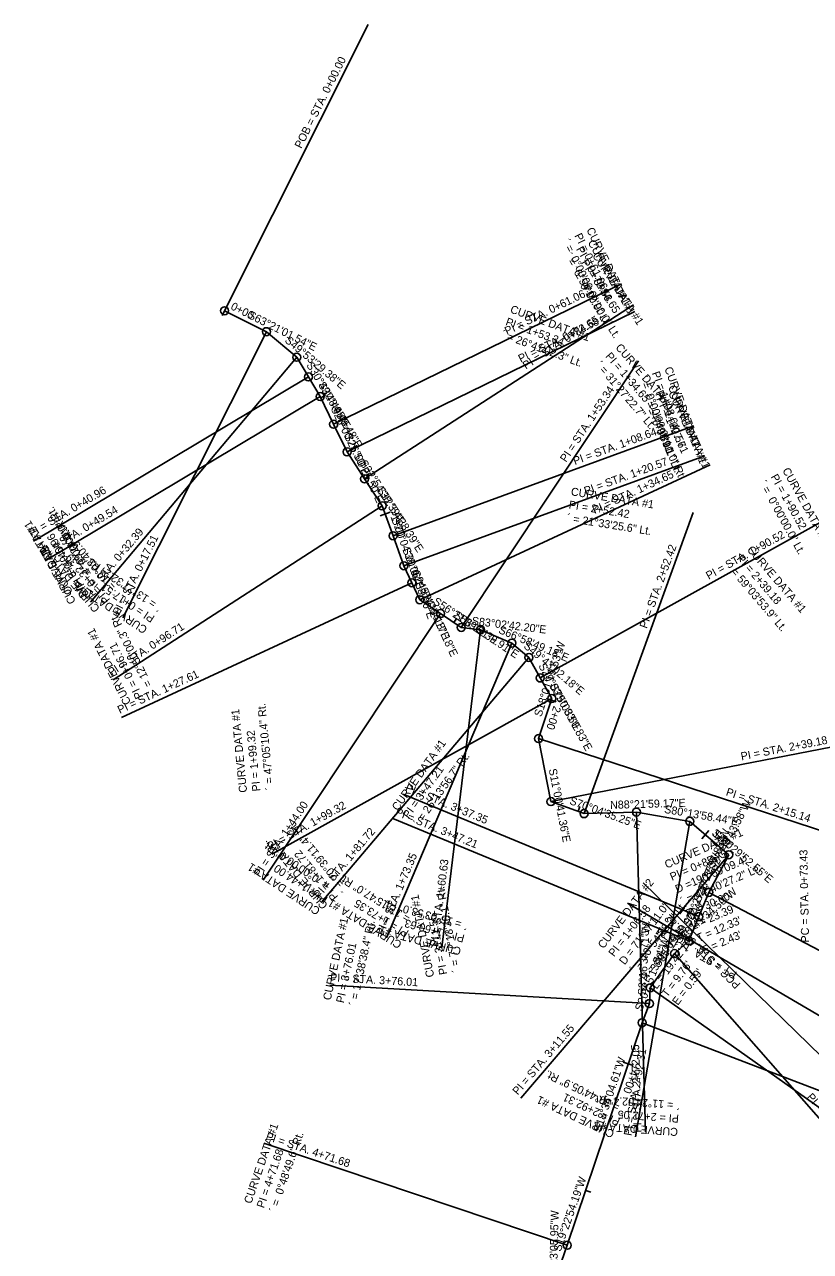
# Model space of a CAD drawing. Extents: x 1158784 to 1165006, y 610007 to 611539.
# Drawn here: x 1162723.7 to 1163018.2, y 610487.8 to 610947.6 of the extents above; entities that cross this region are included whole.
import ezdxf

# ---------------------------------------------------------------- set-up
doc = ezdxf.new("R2010")
doc.units = 0
for name, color, linetype in [('D_Roadway_Centerline', 7, 'Continuous'), ('D_Roadway_Centerline_Bearings', 7, 'Continuous'), ('D_Roadway_Centerline_CurveData', 7, 'Continuous'), ('D_Roadway_Centerline_Flags', 7, 'Continuous'), ('D_Roadway_Centerline_Text', 7, 'Continuous')]:
    doc.layers.add(name, color=color, linetype=linetype)

msp = doc.modelspace()

# ---------------------------------------------------------------- linework, layer by layer
at = {"layer": 'D_Roadway_Centerline'}
for p, q in [((1162798.64, 610840.35), (1162814.29, 610832.5)), ((1162814.29, 610832.5), (1162825.67, 610822.91)), ((1162825.67, 610822.91), (1162830.06, 610815.55)), ((1162830.06, 610815.55), (1162834.46, 610808.18)), ((1162834.46, 610808.18), (1162839.51, 610797.83)), ((1162839.51, 610797.83), (1162844.56, 610787.47)), ((1162844.56, 610787.47), (1162851.11, 610777.35)), ((1162851.11, 610777.35), (1162857.67, 610767.22)), ((1162857.67, 610767.22), (1162861.76, 610756.01)), ((1162861.76, 610756.01), (1162865.86, 610744.8)), ((1162865.86, 610744.8), (1162868.83, 610738.42)), ((1162868.83, 610738.42), (1162871.79, 610732.03)), ((1162871.79, 610732.03), (1162879.57, 610726.86)), ((1162879.57, 610726.86), (1162887.35, 610721.68)), ((1162887.35, 610721.68), (1162894.58, 610720.8)), ((1162894.58, 610720.8), (1162906.29, 610715.82)), ((1162906.29, 610715.82), (1162912.68, 610710.41)), ((1162912.68, 610710.41), (1162916.95, 610702.72)), ((1162916.95, 610702.72), (1162921.23, 610695.03)), ((1162921.23, 610695.03), (1162916.33, 610679.99)), ((1162916.33, 610679.99), (1162920.92, 610656.39)), ((1162920.92, 610656.39), (1162933.37, 610651.88)), ((1162933.37, 610651.88), (1162953, 610652.44)), ((1162953, 610652.44), (1162972.95, 610649)), ((1162972.95, 610649), (1162987.59, 610636.5)), ((1162987.59, 610636.5), (1162980.17, 610622.39)), ((1162980.17, 610622.39), (1162976.4, 610613.28)), ((1162976.4, 610613.28), (1162972.64, 610604.17)), ((1162972.64, 610604.17), (1162967.25, 610599.44)), ((1162967.25, 610599.44), (1162958.16, 610586.62)), ((1162958.16, 610586.62), (1162957.82, 610580.71)), ((1162957.82, 610580.71), (1162955.09, 610573.54)), ((1162955.09, 610573.54), (1162927.06, 610490.12)), ((1162927.06, 610490.12), (1162924.92, 610484.02))]:
    msp.add_line(p, q, dxfattribs=at)
at = {"layer": 'D_Roadway_Centerline_Flags'}
for points in [[(1162798.64, 610840.35), (1162852.46, 610947.6)], [(1162839.51, 610797.83), (1162947.36, 610850.44)], [(1162844.56, 610787.47), (1162952.41, 610840.09)], [(1162851.11, 610777.35), (1162951.86, 610842.54)], [(1162814.29, 610832.5), (1162760.46, 610725.24)], [(1162825.67, 610822.91), (1162748.36, 610731.13)], [(1162887.35, 610721.68), (1162953.82, 610821.59)], [(1162830.06, 610815.55), (1162727.02, 610754.05)], [(1162834.46, 610808.18), (1162731.41, 610746.68)], [(1162861.76, 610756.01), (1162974.47, 610797.21)], [(1162865.86, 610744.8), (1162978.57, 610786)], [(1162871.79, 610732.03), (1162980.63, 610782.57)], [(1162857.67, 610767.22), (1162756.93, 610702.02)], [(1162933.37, 610651.88), (1162974.26, 610764.7)], [(1162916.95, 610702.72), (1163021.84, 610761.02)], [(1162868.83, 610738.42), (1162759.98, 610687.89)], [(1162879.57, 610726.86), (1162813.09, 610626.95)], [(1162894.58, 610720.8), (1162880.05, 610601.68)], [(1162906.29, 610715.82), (1162859.37, 610605.38)], [(1162912.68, 610710.41), (1162835.09, 610618.87)], [(1162921.23, 610695.03), (1162816.34, 610636.74)], [(1162916.33, 610679.99), (1163030.44, 610642.86)], [(1162920.92, 610656.39), (1163038.71, 610679.31)], [(1162976.4, 610613.28), (1162865.5, 610659.13)], [(1162953, 610652.44), (1162956.42, 610532.49)], [(1162972.64, 610604.17), (1162861.74, 610650.02)], [(1162972.95, 610649), (1162952.6, 610530.74)], [(1162987.59, 610636.5), (1162909.65, 610545.26)], [(1163041.46, 610542.25), (1162955.5, 610625.98)], [(1162980.17, 610622.39), (1163086.39, 610566.56)], [(1163053.2, 610557.66), (1162949.63, 610618.28)], [(1162967.25, 610599.44), (1163046.46, 610509.29)], [(1162957.82, 610580.71), (1162838.02, 610587.57)], [(1162958.16, 610586.62), (1163056.06, 610517.22)], [(1162955.09, 610573.54), (1163067.17, 610530.69)], [(1162927.06, 610490.12), (1162813.31, 610528.33)]]:
    msp.add_lwpolyline(points, dxfattribs=at)
for centre in [(1162798.64, 610840.35), (1162814.29, 610832.5), (1162825.67, 610822.91), (1162830.06, 610815.55), (1162834.46, 610808.18), (1162839.51, 610797.83), (1162844.56, 610787.47), (1162851.11, 610777.35), (1162857.67, 610767.22), (1162861.76, 610756.01), (1162865.86, 610744.8), (1162868.83, 610738.42), (1162871.79, 610732.03), (1162879.57, 610726.86), (1162887.35, 610721.68), (1162894.58, 610720.8), (1162906.29, 610715.82), (1162912.68, 610710.41), (1162916.95, 610702.72), (1162921.23, 610695.03), (1162916.33, 610679.99), (1162920.92, 610656.39), (1162933.37, 610651.88), (1162953, 610652.44), (1162972.95, 610649), (1162987.59, 610636.5), (1162980.17, 610622.39), (1162976.4, 610613.28), (1162972.64, 610604.17), (1162967.25, 610599.44), (1162958.16, 610586.62), (1162957.82, 610580.71), (1162955.09, 610573.54), (1162927.06, 610490.12)]:
    msp.add_circle(centre, 1.5, dxfattribs=at)
at = {"layer": 'D_Roadway_Centerline_Text'}
for points in [[(1162799.54, 610842.14), (1162797.74, 610838.56)], [(1162836.46, 610808.65), (1162834.66, 610807.77)], [(1162860.68, 610764.81), (1162856.92, 610763.44)], [(1162885.67, 610725.2), (1162884.57, 610723.53)], [(1162922.92, 610693.77), (1162919.11, 610695)], [(1162931.78, 610654.58), (1162931.09, 610652.7)], [(1162980.1, 610645.53), (1162977.51, 610642.48)], [(1162971.86, 610600.83), (1162970.54, 610602.33)], [(1162951.79, 610557.44), (1162947.99, 610558.71)], [(1162935.86, 610510.04), (1162933.97, 610510.68)]]:
    msp.add_lwpolyline(points, dxfattribs=at)

# ---------------------------------------------------------------- texts
at = {"layer": 'D_Roadway_Centerline_Bearings'}
for s, rotation, p in [('S63%%d21\'01.54"E', 333.3504, (1162807.13, 610837.76)), ('S49%%d53\'29.38"E', 319.8915, (1162820.94, 610828.85)), ('S30%%d49\'48.48"E', 300.8301, (1162829.15, 610820)), ('S30%%d49\'48.48"E', 300.8301, (1162833.55, 610812.63)), ('S26%%d00\'25.50"E', 296.0071, (1162838.33, 610803.66)), ('S26%%d00\'25.50"E', 296.0071, (1162843.38, 610793.31)), ('S32%%d54\'38.39"E', 302.9107, (1162849.1, 610783.22)), ('S32%%d54\'38.39"E', 302.9107, (1162855.65, 610773.1)), ('S20%%d04\'38.06"E', 290.0772, (1162861.13, 610762.13)), ('S20%%d04\'38.06"E', 290.0772, (1162865.22, 610750.92)), ('S24%%d54\'17.18"E', 294.9048, (1162868.7, 610742.24)), ('S24%%d54\'17.18"E', 294.9048, (1162871.67, 610735.86)), ('S56%%d21\'39.91"E', 326.3611, (1162876.51, 610730.69)), ('S56%%d21\'39.91"E', 326.3611, (1162884.29, 610725.52)), ('S83%%d02\'42.20"E', 353.0451, (1162891.15, 610722.73)), ('S66%%d58\'49.18"E', 336.9803, (1162901.03, 610719.69)), ('S49%%d43\'02.18"E', 319.7173, (1162910.46, 610714.26)), ('S18%%d01\'19.53"W', 71.9779, (1162917.35, 610687.98)), ('S29%%d03\'50.83"E', 299.0641, (1162916.13, 610707.3)), ('S29%%d03\'50.83"E', 299.0641, (1162920.4, 610699.61)), ('S11%%d00\'41.36"E', 281.0115, (1162920.1, 610668.48)), ('S70%%d04\'35.25"E', 340.0765, (1162927.66, 610655.54)), ('N88%%d21\'59.17"E', 1.6336, (1162943.14, 610653.66)), ('S27%%d43\'43.58"W', 62.2712, (1162982.55, 610630.15)), ('S80%%d13\'58.44"E', 350.2329, (1162963.23, 610652.2)), ('S22%%d27\'37.85"W', 67.5395, (1162976.9, 610618.41)), ('S49%%d29\'52.55"E', 319.4979, (1162981.24, 610643.89)), ('S22%%d27\'37.85"W', 67.5395, (1162973.13, 610609.3)), ('S48%%d41\'34.50"W', 41.3071, (1162968.95, 610602.93)), ('S35%%d19\'49.90"W', 54.6695, (1162961.48, 610593.9)), ('S3%%d16\'34.71"W', 86.7237, (1162956.5, 610583.75)), ('S20%%d55\'13.14"W', 69.0797, (1162955.05, 610577.66)), ('S18%%d34\'04.61"W', 71.4321, (1162939.65, 610532.31)), ('S19%%d22\'54.19"W', 70.6183, (1162924.57, 610487.57)), ('S1%%d23\'05.95"W', 88.615, (1162923.23, 610476.17))]:
    msp.add_text(s, height=3, rotation=rotation, dxfattribs=at).set_placement(p)
at = {"layer": 'D_Roadway_Centerline_CurveData'}
for s, rotation, p in [('´ =  0%%d00\'00.0" Lt.', 296.0071, (1162925.15, 610866.31)), ('PI = 0+61.06', 296.0071, (1162929.64, 610868.51)), ('CURVE DATA #1', 296.0071, (1162934.14, 610870.7)), ('PI = 0+72.58', 299.4589, (1162930.28, 610863.45)), ('CURVE DATA #1', 299.4589, (1162934.63, 610865.91)), ('´ =  6%%d54\'12.9" Lt.', 299.4589, (1162925.92, 610860.99)), ('PI = 0+84.65', 302.9107, (1162932.1, 610858.35)), ('CURVE DATA #1', 302.9107, (1162936.3, 610861.06)), ('´ =  0%%d00\'00.0" Lt.', 302.9107, (1162927.9, 610855.63)), ('CURVE DATA #1', 339.7031, (1162905.42, 610839.74)), ('PI = 1+53.34', 339.7031, (1162903.69, 610835.05)), ('´ = 26%%d41\'02.3" Lt.', 339.7031, (1162901.95, 610830.36)), ('CURVE DATA #1', 310.6329, (1162944.95, 610826.44)), ('´ = 31%%d27\'22.7" Lt.', 310.6329, (1162937.36, 610819.93)), ('PI = 1+34.65', 310.6329, (1162941.16, 610823.18)), ('PI = 1+08.64', 290.0772, (1162958.72, 610817)), ('CURVE DATA #1', 290.0772, (1162963.42, 610818.72)), ('´ =  0%%d00\'00.0" Lt.', 290.0772, (1162954.02, 610815.28)), ('CURVE DATA #1', 292.491, (1162964.78, 610811.74)), ('´ =  4%%d49\'39.1" Lt.', 292.491, (1162955.54, 610807.91)), ('PI = 1+20.57', 292.491, (1162960.16, 610809.82)), ('PI = 1+27.61', 294.9048, (1162960.3, 610807.35)), ('CURVE DATA #1', 294.9048, (1162964.84, 610809.46)), ('´ =  0%%d00\'00.0" Rt.', 294.9048, (1162955.77, 610805.25)), ('CURVE DATA #1', 299.0641, (1163007.56, 610780.54)), ('´ =  0%%d00\'00.0" Lt.', 299.0641, (1162998.82, 610775.68)), ('PI = 1+90.52', 299.0641, (1163003.19, 610778.11)), ('CURVE DATA #1', 350.855, (1162928.27, 610771.21)), ('´ =  0%%d00\'00.0" Rt.', 120.8301, (1162750.48, 610740.1)), ('PI = 2+52.42', 350.855, (1162927.47, 610766.27)), ('CURVE DATA #1', 120.8301, (1162741.89, 610734.98)), ('´ =  4%%d49\'23.0" Rt.', 118.4186, (1162751.77, 610736.15)), ('´ = 21%%d33\'25.6" Lt.', 350.855, (1162926.68, 610761.33)), ('CURVE DATA #1', 118.4186, (1162742.98, 610731.39)), ('´ = 19%%d03\'40.9" Rt.', 130.3608, (1162759.68, 610735.33)), ('CURVE DATA #1', 130.3608, (1162752.06, 610728.86)), ('PI = 0+40.96', 120.8301, (1162746.19, 610737.54)), ('PI = 0+49.54', 118.4186, (1162747.37, 610733.77)), ('PI = 0+32.39', 130.3608, (1162755.87, 610732.09)), ('´ = 13%%d27\'32.2" Rt.', 146.621, (1162775.46, 610729.94)), ('PI = 2+39.18', 310.544, (1162990.43, 610747.43)), ('CURVE DATA #1', 310.544, (1162994.23, 610750.68)), ('´ = 59%%d03\'53.9" Lt.', 310.544, (1162986.63, 610744.18)), ('CURVE DATA #1', 146.621, (1162769.96, 610721.59)), ('PI = 0+17.51', 146.621, (1162772.71, 610725.77)), ('´ = 12%%d50\'00.3" Rt.', 116.494, (1162772.61, 610698.01)), ('CURVE DATA #1', 116.494, (1162763.66, 610693.54)), ('PI = 0+96.71', 116.494, (1162768.14, 610695.78)), ('´ = 47%%d05\'10.4" Rt.', 95.521, (1162817.03, 610660.85)), ('CURVE DATA #1', 95.521, (1162807.08, 610659.89)), ('PI = 1+99.32', 95.521, (1162812.05, 610660.37)), ('CURVE DATA #1', 54.4233, (1162863.51, 610652.72)), ('PI = 3+47.21', 54.4233, (1162867.58, 610649.81)), ('´ = 26%%d13\'56.7" Rt.', 54.4233, (1162871.65, 610646.9)), ('´ = 20%%d39\'11.4" Rt.', 129.3907, (1162845.22, 610623.96)), ('CURVE DATA #1', 23.4148, (1162964.34, 610631.25)), ('´ =  0%%d00\'00.0" Rt.', 146.3611, (1162840.28, 610624.48)), ('CURVE DATA #1', 129.3907, (1162837.49, 610617.62)), ('PI = 1+81.72', 129.3907, (1162841.35, 610620.79)), ('PI = 0+85.75', 23.4148, (1162966.32, 610626.66)), ('CURVE DATA #1', 146.3611, (1162834.74, 610616.15)), ('D =190%%d59\'09.4"', 23.4148, (1162968.31, 610622.07)), ('PI = 1+44.00', 146.3611, (1162837.51, 610620.32)), ('´ = 17%%d15\'47.0" Rt.', 148.3488, (1162870.58, 610612.15)), ('´ = 44%%d40\'27.2" Lt.', 23.4148, (1162970.3, 610617.48)), ('´ = 77%%d13\'36.1" Rt.', 100.8846, (1162887.04, 610592.73)), ('CURVE DATA #2', 52.7073, (1162940.65, 610601.04)), ('CURVE DATA #1', 148.3488, (1162865.33, 610603.63)), ('PI = 1+73.35', 148.3488, (1162867.95, 610607.89)), ('´ = 16%%d03\'53.0" Rt.', 165.0127, (1162890.1, 610611.23)), ('CURVE DATA #1', 100.8846, (1162877.22, 610590.84)), ("R = 30.00'", 23.4148, (1162972.29, 610612.9)), ('PI = 1+06.58', 52.7073, (1162944.62, 610598.01)), ('D = 71%%d37\'11.0"', 52.7073, (1162948.6, 610594.98)), ('´ = 13%%d54\'38.3" Lt.', 52.7073, (1162952.58, 610591.95)), ("L = 23.39'", 23.4148, (1162974.27, 610608.31)), ('CURVE DATA #1', 77.9017, (1162838.39, 610581.76)), ('´ = 17%%d38\'38.4" Rt.', 77.9017, (1162848.17, 610579.67)), ('PI = 1+60.63', 165.0127, (1162888.8, 610606.4)), ('PI = 3+11.55', 100.8846, (1162882.13, 610591.79)), ("T = 12.33'", 23.4148, (1162976.26, 610603.72)), ('CURVE DATA #1', 165.0127, (1162887.51, 610601.57)), ("E = 2.43'", 23.4148, (1162978.25, 610599.13)), ('PI = 3+76.01', 77.9017, (1162843.28, 610580.72)), ("R = 80.00'", 52.7073, (1162956.56, 610588.92)), ("L = 19.42'", 52.7073, (1162960.54, 610585.89)), ("T = 9.76'", 52.7073, (1162964.51, 610582.86)), ("E = 0.59'", 52.7073, (1162968.49, 610579.83)), ('´ = 30%%d44\'05.9" Rt.', 154.8654, (1162949.23, 610541.94)), ('CURVE DATA #1', 154.8654, (1162944.99, 610532.89)), ('PI = 2+92.31', 154.8654, (1162947.11, 610537.41)), ('´ = 11%%d24\'02.4" Rt.', 175.9332, (1162969.35, 610544.01)), ('CURVE DATA #1', 175.9332, (1162968.64, 610534.03)), ('PI = 2+72.05', 175.9332, (1162968.99, 610539.02)), ('CURVE DATA #1', 71.0252, (1162808.62, 610505.47)), ('´ =  0%%d48\'49.6" Rt.', 71.0252, (1162818.07, 610502.22)), ('PI = 4+71.68', 71.0252, (1162813.35, 610503.84))]:
    msp.add_text(s, height=3, rotation=rotation, dxfattribs=at).set_placement(p)
at = {"layer": 'D_Roadway_Centerline_Flags'}
for s, rotation, p in [('POB = STA. 0+00.00', 63.3504, (1162827.36, 610900.92)), ('PI = STA. 0+61.06', 26.0071, (1162904.49, 610831.2)), ('PI = STA. 0+72.58', 26.0071, (1162909.6, 610820.87)), ('PI = STA. 0+84.65', 32.9107, (1162911.56, 610818.25)), ('PI = STA. 1+53.34', 56.3611, (1162926.59, 610783.37)), ('PI = STA. 1+08.64', 20.0772, (1162929.91, 610782.51)), ('PI = STA. 1+20.57', 20.0772, (1162934, 610771.31)), ('PI = STA. 1+34.65', 24.9048, (1162937.34, 610764.12)), ('PI = STA. 0+40.96', 30.8301, (1162726.25, 610755.34)), ('PI = STA. 0+49.54', 30.8301, (1162730.64, 610747.97)), ('PI = STA. 0+32.39', 49.8915, (1162747.21, 610732.1)), ('PI = STA. 1+90.52', 29.0641, (1162980.06, 610739.51)), ('PI = STA. 0+17.51', 63.3504, (1162759.12, 610725.92)), ('PI = STA. 2+52.42', 70.0765, (1162956.84, 610721.05)), ('PI = STA. 0+96.71', 32.9107, (1162756.11, 610703.28)), ('PI = STA. 1+27.61', 24.9048, (1162759.35, 610689.25)), ('PI = STA. 2+39.18', 11.0115, (1162992.39, 610671.82)), ('PI = STA. 3+37.35', 337.5395, (1162866.08, 610660.51)), ('PI = STA. 2+15.14', 341.9779, (1162986.31, 610658.8)), ('PI = STA. 1+44.00', 56.3611, (1162811.84, 610627.78)), ('PI = STA. 1+99.32', 29.0641, (1162815.61, 610638.05)), ('PI = STA. 3+47.21', 337.5395, (1162862.31, 610651.4)), ('PI = STA. 1+81.72', 49.7173, (1162833.95, 610619.84)), ('PC = STA. 0+73.43', 91.0777, (1163017.71, 610603.62)), ('PI = STA. 1+73.35', 66.9803, (1162857.99, 610605.97)), ('PI = STA. 1+60.63', 83.0451, (1162878.56, 610601.86)), ('PCC = STA. 0+96.82', 135.752, (1162992.24, 610588.1)), ('PT = STA. 1+16.24', 149.6626, (1162990.9, 610592.38)), ('PI = STA. 3+76.01', 356.7237, (1162838.11, 610589.07)), ('PI = STA. 3+11.55', 49.4979, (1162908.51, 610546.23)), ('PI = STA. 2+72.05', 91.6336, (1162954.92, 610532.44)), ('PI = STA. 2+92.31', 80.2329, (1162951.12, 610531)), ('PI = STA. 3+54.38', 311.3071, (1163016.63, 610545.52)), ('PI = STA. 4+71.68', 341.4321, (1162813.79, 610529.76))]:
    msp.add_text(s, height=3, rotation=rotation, dxfattribs=at).set_placement(p)
at = {"layer": 'D_Roadway_Centerline_Text'}
for s, rotation, p in [('0+00', 333.3504, (1162800.65, 610841.02)), ('1+00', 290.0772, (1162860.72, 610763.23)), ('2+00', 251.9779, (1162921.98, 610692.49)), ('3+00', 319.4979, (1162980.92, 610644.17)), ('4+00', 251.4321, (1162950.83, 610556.18))]:
    msp.add_text(s, height=3, rotation=rotation, dxfattribs=at).set_placement(p)

doc.saveas('drawing.dxf')
